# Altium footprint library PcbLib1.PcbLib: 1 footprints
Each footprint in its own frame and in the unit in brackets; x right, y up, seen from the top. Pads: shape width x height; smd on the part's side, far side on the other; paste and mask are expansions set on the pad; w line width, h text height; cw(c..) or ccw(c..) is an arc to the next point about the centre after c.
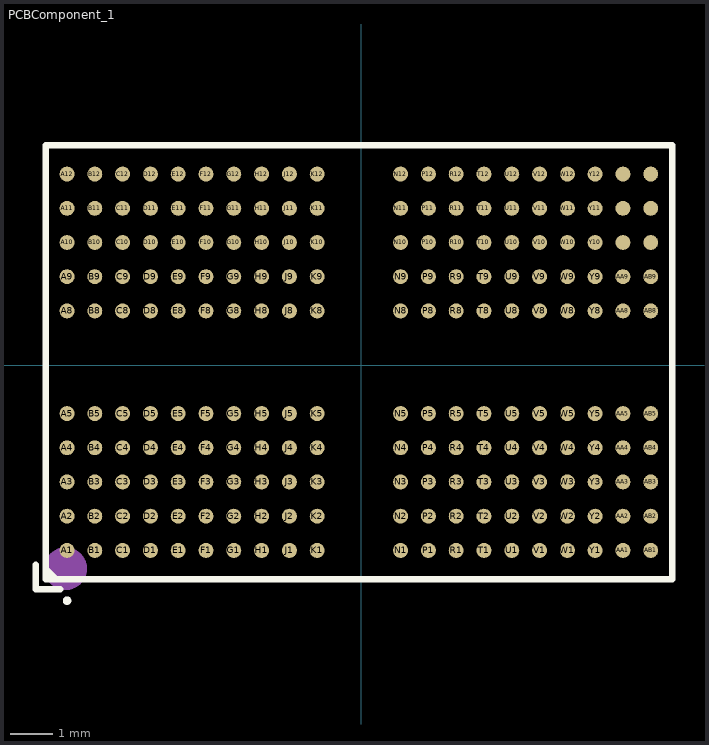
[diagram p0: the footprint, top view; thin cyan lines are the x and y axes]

## PCBComponent_1 [mm]
pads (200):
  round 0.35 smd paste+0 mask+0.025: A1(-6.877,-4.324) A2(-6.877,-3.524) A3(-6.877,-2.724) A4(-6.877,-1.924) A5(-6.877,-1.124) A8(-6.877,1.276) A9(-6.877,2.076) A10(-6.877,2.876) A11(-6.877,3.676) A12(-6.877,4.476) AA1(6.123,-4.324) AA2(6.123,-3.524) AA3(6.123,-2.724) AA4(6.123,-1.924) AA5(6.123,-1.124) AA8(6.123,1.276) AA9(6.123,2.076) AA10(6.123,2.876) AA11(6.123,3.676) AA12(6.123,4.476) AB1(6.773,-4.324) AB2(6.773,-3.524) AB3(6.773,-2.724) AB4(6.773,-1.924) AB5(6.773,-1.124) AB8(6.773,1.276) AB9(6.773,2.076) AB10(6.773,2.876) AB11(6.773,3.676) AB12(6.773,4.476) B1(-6.227,-4.324) B2(-6.227,-3.524) B3(-6.227,-2.724) B4(-6.227,-1.924) B5(-6.227,-1.124) B8(-6.227,1.276) B9(-6.227,2.076) B10(-6.227,2.876) B11(-6.227,3.676) B12(-6.227,4.476) C1(-5.577,-4.324) C2(-5.577,-3.524) C3(-5.577,-2.724) C4(-5.577,-1.924) C5(-5.577,-1.124) C8(-5.577,1.276) C9(-5.577,2.076) C10(-5.577,2.876) C11(-5.577,3.676) C12(-5.577,4.476) D1(-4.927,-4.324) D2(-4.927,-3.524) D3(-4.927,-2.724) D4(-4.927,-1.924) D5(-4.927,-1.124) D8(-4.927,1.276) D9(-4.927,2.076) D10(-4.927,2.876) D11(-4.927,3.676) D12(-4.927,4.476) E1(-4.277,-4.324) E2(-4.277,-3.524) E3(-4.277,-2.724) E4(-4.277,-1.924) E5(-4.277,-1.124) E8(-4.277,1.276) E9(-4.277,2.076) E10(-4.277,2.876) E11(-4.277,3.676) E12(-4.277,4.476) F1(-3.627,-4.324) F2(-3.627,-3.524) F3(-3.627,-2.724) F4(-3.627,-1.924) F5(-3.627,-1.124) F8(-3.627,1.276) F9(-3.627,2.076) F10(-3.627,2.876) F11(-3.627,3.676) F12(-3.627,4.476) G1(-2.977,-4.324) G2(-2.977,-3.524) G3(-2.977,-2.724) G4(-2.977,-1.924) G5(-2.977,-1.124) G8(-2.977,1.276) G9(-2.977,2.076) G10(-2.977,2.876) G11(-2.977,3.676) G12(-2.977,4.476) H1(-2.327,-4.324) H2(-2.327,-3.524) H3(-2.327,-2.724) H4(-2.327,-1.924) H5(-2.327,-1.124) H8(-2.327,1.276) H9(-2.327,2.076) H10(-2.327,2.876) H11(-2.327,3.676) H12(-2.327,4.476) J1(-1.677,-4.324) J2(-1.677,-3.524) J3(-1.677,-2.724) J4(-1.677,-1.924) J5(-1.677,-1.124) J8(-1.677,1.276) J9(-1.677,2.076) J10(-1.677,2.876) J11(-1.677,3.676) J12(-1.677,4.476) K1(-1.027,-4.324) K2(-1.027,-3.524) K3(-1.027,-2.724) K4(-1.027,-1.924) K5(-1.027,-1.124) K8(-1.027,1.276) K9(-1.027,2.076) K10(-1.027,2.876) K11(-1.027,3.676) K12(-1.027,4.476) N1(0.923,-4.324) N2(0.923,-3.524) N3(0.923,-2.724) N4(0.923,-1.924) N5(0.923,-1.124) N8(0.923,1.276) N9(0.923,2.076) N10(0.923,2.876) N11(0.923,3.676) N12(0.923,4.476) P1(1.573,-4.324) P2(1.573,-3.524) P3(1.573,-2.724) P4(1.573,-1.924) P5(1.573,-1.124) P8(1.573,1.276) P9(1.573,2.076) P10(1.573,2.876) P11(1.573,3.676) P12(1.573,4.476) R1(2.223,-4.324) R2(2.223,-3.524) R3(2.223,-2.724) R4(2.223,-1.924) R5(2.223,-1.124) R8(2.223,1.276) R9(2.223,2.076) R10(2.223,2.876) R11(2.223,3.676) R12(2.223,4.476) T1(2.873,-4.324) T2(2.873,-3.524) T3(2.873,-2.724) T4(2.873,-1.924) T5(2.873,-1.124) T8(2.873,1.276) T9(2.873,2.076) T10(2.873,2.876) T11(2.873,3.676) T12(2.873,4.476) U1(3.523,-4.324) U2(3.523,-3.524) U3(3.523,-2.724) U4(3.523,-1.924) U5(3.523,-1.124) U8(3.523,1.276) U9(3.523,2.076) U10(3.523,2.876) U11(3.523,3.676) U12(3.523,4.476) V1(4.173,-4.324) V2(4.173,-3.524) V3(4.173,-2.724) V4(4.173,-1.924) V5(4.173,-1.124) V8(4.173,1.276) V9(4.173,2.076) V10(4.173,2.876) V11(4.173,3.676) V12(4.173,4.476) W1(4.823,-4.324) W2(4.823,-3.524) W3(4.823,-2.724) W4(4.823,-1.924) W5(4.823,-1.124) W8(4.823,1.276) W9(4.823,2.076) W10(4.823,2.876) W11(4.823,3.676) W12(4.823,4.476) Y1(5.473,-4.324) Y2(5.473,-3.524) Y3(5.473,-2.724) Y4(5.473,-1.924) Y5(5.473,-1.124) Y8(5.473,1.276) Y9(5.473,2.076) Y10(5.473,2.876) Y11(5.473,3.676) Y12(5.473,4.476)
Top Overlay:
  circle w0.1: c-6.877,-5.5 r0.05
  region: -7.379,-5 -7.039,-5 -7.379,-4.66
  lines w0.152: -7.607,-4.66 -7.607,-5.229 -7.039,-5.229 ; -7.379,-5 -7.379,5.152 7.274,5.152 7.274,-5 -7.379,-5
Mechanical 15:
  circle w0.5: c-6.91,-4.75 r0.25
